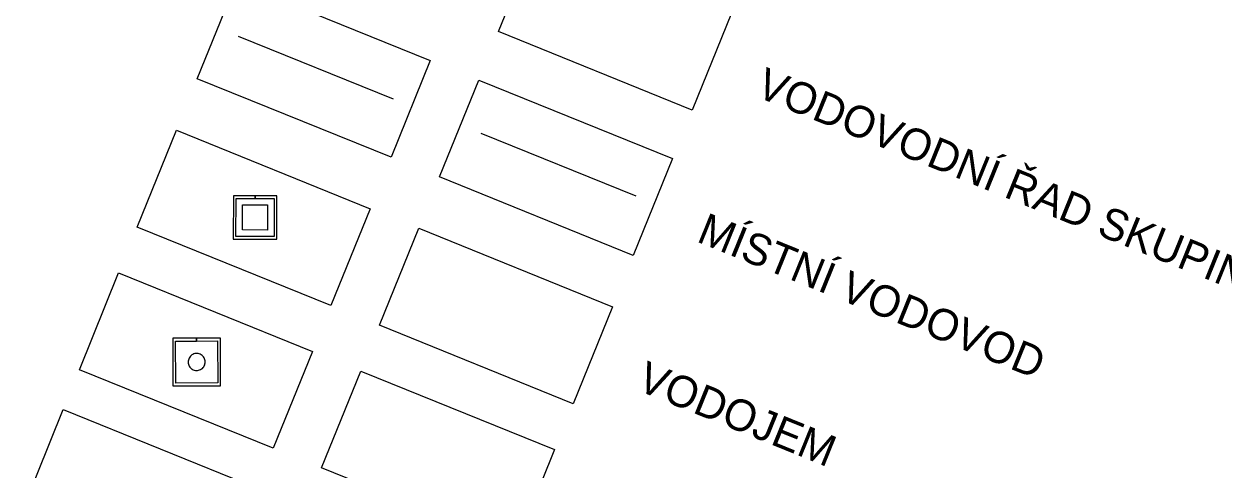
# Model space of a CAD drawing. Extents: x -522797 to -519326, y -1191143 to -1184078.
# Drawn here: x -521587 to -521013, y -1189504 to -1189290 of the extents above; entities that cross this region are included whole.
import ezdxf

# ---------------------------------------------------------------- set-up
doc = ezdxf.new("R2010")
doc.units = 0
for name, color, linetype in [('Implicitní', 7, 'Continuous'), ('ložisk_nerost', 7, 'Continuous'), ('zast_HD_s', 7, 'Continuous')]:
    doc.layers.add(name, color=color, linetype=linetype)

msp = doc.modelspace()

# ---------------------------------------------------------------- linework, layer by layer
at = {"layer": 'Implicitní'}
for p, q in [((-521484.76, -1189296.08), (-521410.62, -1189326.13)), ((-521368.72, -1189342.47), (-521294.58, -1189372.52))]:
    msp.add_line(p, q, dxfattribs=at)
for points in [[(-521341.56, -1189247.62), (-521248.89, -1189285.18), (-521267.67, -1189331.52), (-521360.34, -1189293.96)], [(-521485.58, -1189270.18), (-521392.9, -1189307.74), (-521411.68, -1189354.08), (-521504.36, -1189316.52)], [(-521369.73, -1189317.13), (-521277.06, -1189354.69), (-521295.84, -1189401.03), (-521388.52, -1189363.47)], [(-521514.32, -1189341.09), (-521421.64, -1189378.65), (-521440.42, -1189424.99), (-521533.1, -1189387.42)], [(-521398.47, -1189388.04), (-521305.8, -1189425.6), (-521324.58, -1189471.94), (-521417.25, -1189434.38)], [(-521541.98, -1189409.34), (-521449.3, -1189446.9), (-521468.09, -1189493.24), (-521560.76, -1189455.68)], [(-521426.14, -1189456.29), (-521333.46, -1189493.85), (-521352.24, -1189540.19), (-521444.92, -1189502.63)], [(-521568.47, -1189474.7), (-521475.79, -1189512.26), (-521494.57, -1189558.6), (-521587.25, -1189521.04)]]:
    msp.add_lwpolyline(points, close=True, dxfattribs=at)
at = {"layer": 'ložisk_nerost'}
for points in [[(-521504.72, -1189440.53), (-521516.13, -1189440.56), (-521516.08, -1189463.44), (-521493.2, -1189463.39), (-521493.25, -1189440.51), (-521504.69, -1189440.53)], [(-521504.72, -1189441.94), (-521504.72, -1189440.53)], [(-521504.69, -1189440.53), (-521504.69, -1189441.94)], [(-521514.72, -1189441.97), (-521494.66, -1189441.92), (-521494.61, -1189461.98), (-521514.68, -1189462.03), (-521514.72, -1189441.97)], [(-521504.69, -1189441.94), (-521494.66, -1189441.92), (-521494.61, -1189461.98), (-521514.68, -1189462.03), (-521514.72, -1189441.96), (-521504.72, -1189441.94)], [(-521500.6, -1189451.97), (-521500.63, -1189451.45), (-521500.73, -1189450.95), (-521500.89, -1189450.46), (-521501.11, -1189450), (-521501.39, -1189449.56), (-521501.72, -1189449.17), (-521502.1, -1189448.82), (-521502.52, -1189448.52), (-521502.97, -1189448.28), (-521503.45, -1189448.09), (-521503.95, -1189447.97), (-521504.46, -1189447.91), (-521504.98, -1189447.92), (-521505.48, -1189447.99), (-521505.98, -1189448.13), (-521506.46, -1189448.32), (-521506.9, -1189448.58), (-521507.31, -1189448.89), (-521507.68, -1189449.25), (-521508, -1189449.65), (-521508.27, -1189450.09), (-521508.48, -1189450.56), (-521508.63, -1189451.05), (-521508.71, -1189451.56), (-521508.73, -1189452.07), (-521508.69, -1189452.58), (-521508.58, -1189453.08), (-521508.41, -1189453.57), (-521508.18, -1189454.03), (-521507.89, -1189454.45), (-521507.55, -1189454.84), (-521507.16, -1189455.18), (-521506.74, -1189455.47), (-521506.28, -1189455.71), (-521505.8, -1189455.88), (-521505.3, -1189455.99), (-521504.78, -1189456.04), (-521504.27, -1189456.02), (-521503.76, -1189455.94), (-521503.27, -1189455.79), (-521502.8, -1189455.59), (-521502.36, -1189455.32), (-521501.95, -1189455.01), (-521501.59, -1189454.64), (-521501.28, -1189454.23), (-521501.02, -1189453.78), (-521500.83, -1189453.31), (-521500.69, -1189452.82), (-521500.61, -1189452.31), (-521500.6, -1189451.97)]]:
    msp.add_lwpolyline(points, dxfattribs=at)
at = {"layer": 'zast_HD_s'}
for points in [[(-521476.75, -1189372.45), (-521487.12, -1189372.44), (-521487.15, -1189393.24), (-521466.35, -1189393.26), (-521466.32, -1189372.46), (-521476.72, -1189372.45)], [(-521485.84, -1189373.72), (-521467.6, -1189373.75), (-521467.62, -1189391.99), (-521485.86, -1189391.96), (-521485.84, -1189373.72)], [(-521476.72, -1189373.73), (-521467.6, -1189373.74), (-521467.62, -1189391.98), (-521485.86, -1189391.96), (-521485.84, -1189373.72), (-521476.75, -1189373.73)], [(-521482.71, -1189376.86), (-521470.74, -1189376.88), (-521470.76, -1189388.85), (-521482.72, -1189388.83), (-521482.71, -1189376.86)], [(-521476.75, -1189373.73), (-521476.75, -1189372.45)], [(-521476.72, -1189372.45), (-521476.72, -1189373.73)]]:
    msp.add_lwpolyline(points, dxfattribs=at)

# ---------------------------------------------------------------- texts
at = {"layer": 'Implicitní'}
for s, p in [('VODOVODNÍ ŘAD SKUPIN.VODOVODU', (-521237.92, -1189324.69)), ('MÍSTNÍ VODOVOD', (-521266.09, -1189394.2)), ('VODOJEM', (-521294.83, -1189465.11))]:
    msp.add_text(s, height=15, rotation=337.93793, dxfattribs=at).set_placement(p)

doc.saveas('drawing.dxf')
